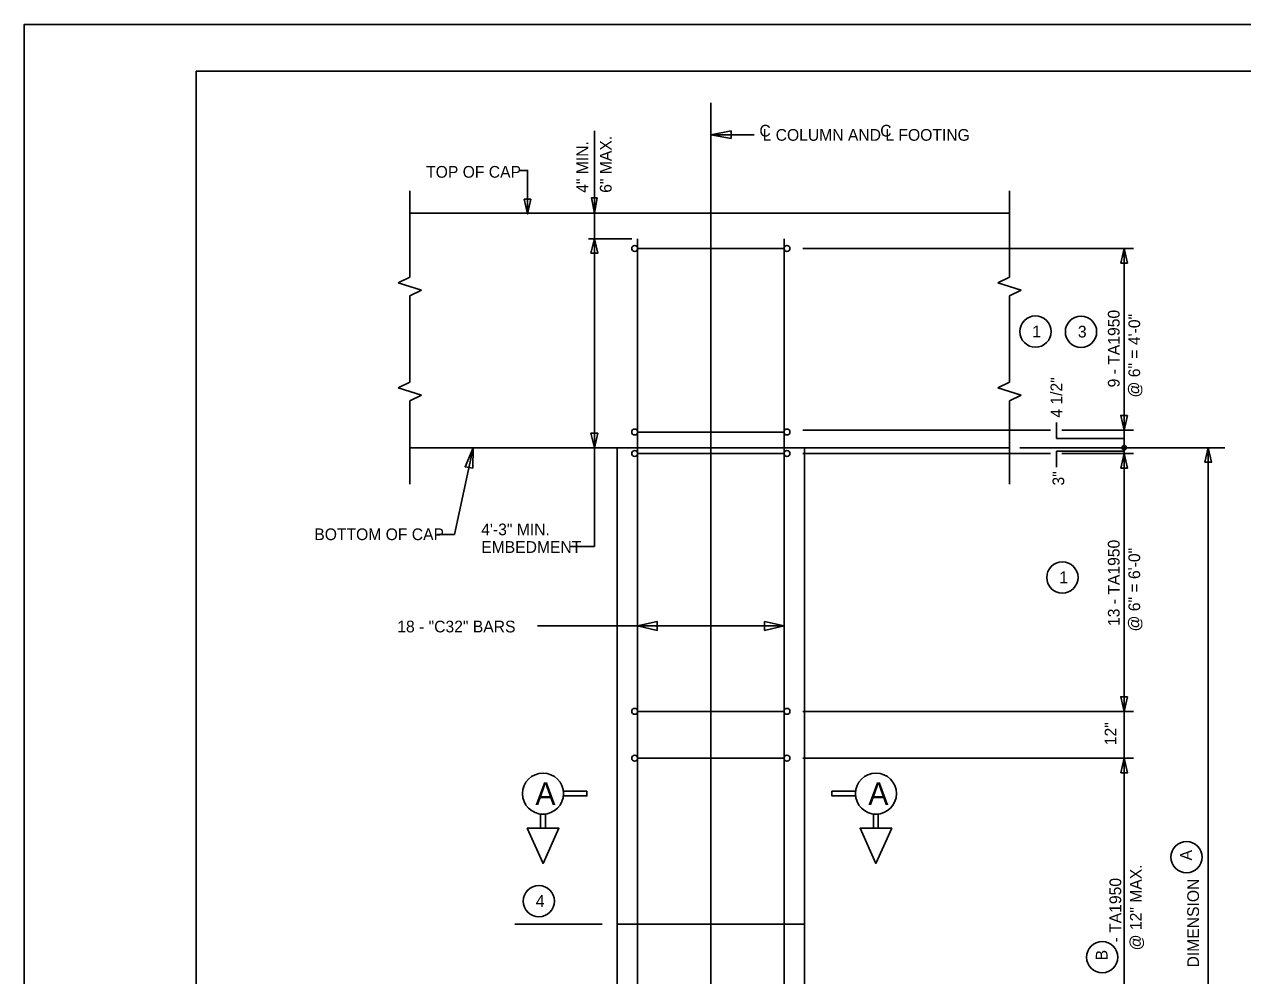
# Model space of a CAD drawing. Extents: x 1970675.2 to 1970711.3, y 796145.2 to 796167.2.
# Drawn here: x 1970675.24 to 1970688.23, y 796157.1 to 796167.25 of the extents above; entities that cross this region are included whole.
import ezdxf

# ---------------------------------------------------------------- set-up
doc = ezdxf.new("R2010")
doc.units = 0
for name, color, linetype in [('BR_AUTO DIMENSION', 7, 'Continuous'), ('BR_BORDER LINES', 7, 'Continuous'), ('BR_CENTER LINES', 7, 'Continuous'), ('BR_CONCRETE', 7, 'Continuous'), ('BR_REBAR', 7, 'Continuous'), ('BR_TEXT', 7, 'Continuous'), ('Default', 7, 'Continuous'), ('Level 31', 7, 'Continuous')]:
    doc.layers.add(name, color=color, linetype=linetype)

msp = doc.modelspace()

# ---------------------------------------------------------------- linework, layer by layer
at = {"layer": 'BR_AUTO DIMENSION'}
for p, q in [((1970681.318, 796166.112), (1970681.318, 796164.961)), ((1970682.561, 796166.069), (1970683.022, 796166.069)), ((1970681.717, 796164.961), (1970681.254, 796164.961)), ((1970681.318, 796164.961), (1970681.318, 796161.677)), ((1970683.541, 796164.857), (1970687.071, 796164.857)), ((1970686.97, 796164.857), (1970686.97, 796153.247)), ((1970686.247, 796162.829), (1970686.247, 796163.002)), ((1970686.97, 796162.92), (1970686.97, 796163.012)), ((1970683.541, 796162.92), (1970686.186, 796162.92)), ((1970686.305, 796162.92), (1970687.071, 796162.92)), ((1970679.827, 796161.807), (1970680.025, 796162.732)), ((1970685.859, 796162.732), (1970688.046, 796162.732)), ((1970686.247, 796162.829), (1970686.97, 796162.829)), ((1970687.866, 796162.732), (1970687.866, 796153.247)), ((1970683.541, 796162.67), (1970686.186, 796162.67)), ((1970686.247, 796162.696), (1970686.97, 796162.696)), ((1970686.247, 796162.696), (1970686.247, 796162.523)), ((1970686.305, 796162.67), (1970687.071, 796162.67)), ((1970686.97, 796162.67), (1970686.97, 796162.543)), ((1970679.64, 796161.807), (1970679.827, 796161.807)), ((1970681.318, 796161.677), (1970681.058, 796161.677)), ((1970680.712, 796160.832), (1970683.342, 796160.832)), ((1970683.541, 796159.92), (1970687.071, 796159.92)), ((1970683.541, 796159.42), (1970687.071, 796159.42)), ((1970680.47, 796157.65), (1970681.4, 796157.65))]:
    msp.add_line(p, q, dxfattribs=at)
for points in [[(1970682.777, 796166.028), (1970682.561, 796166.069), (1970682.777, 796166.111)], [(1970680.641, 796165.381), (1970680.605, 796165.225), (1970680.569, 796165.381)], [(1970681.349, 796165.395), (1970681.318, 796165.232), (1970681.286, 796165.395)], [(1970681.282, 796164.805), (1970681.318, 796164.961), (1970681.354, 796164.805)], [(1970686.934, 796164.701), (1970686.97, 796164.857), (1970687.006, 796164.701)], [(1970687.006, 796163.076), (1970686.97, 796162.92), (1970686.934, 796163.076)], [(1970681.354, 796162.888), (1970681.318, 796162.732), (1970681.282, 796162.888)], [(1970680.02, 796162.512), (1970680.025, 796162.732), (1970679.939, 796162.529)], [(1970687.83, 796162.576), (1970687.866, 796162.732), (1970687.902, 796162.576)], [(1970686.934, 796162.514), (1970686.97, 796162.67), (1970687.006, 796162.514)], [(1970681.987, 796160.784), (1970681.779, 796160.832), (1970681.987, 796160.88)], [(1970683.134, 796160.88), (1970683.342, 796160.832), (1970683.134, 796160.784)], [(1970687.006, 796160.076), (1970686.97, 796159.92), (1970686.934, 796160.076)], [(1970686.934, 796159.264), (1970686.97, 796159.42), (1970687.006, 796159.264)]]:
    msp.add_lwpolyline(points, close=True, dxfattribs=at)
msp.add_lwpolyline([(1970680.605, 796165.225), (1970680.605, 796165.689), (1970680.527, 796165.689)], dxfattribs=at)
for centre, radius in [((1970686.024, 796163.97), 0.167), ((1970686.51, 796163.968), 0.167), ((1970686.97, 796162.732), 0.0235), ((1970686.311, 796161.348), 0.167), ((1970687.636, 796158.365), 0.167), ((1970680.726, 796157.896), 0.167), ((1970686.736, 796157.298), 0.167)]:
    msp.add_circle(centre, radius, dxfattribs=at)
at = {"layer": 'BR_BORDER LINES'}
for p in [(1970710.736, 796166.746), (1970677.07, 796145.746)]:
    msp.add_line(p, (1970677.07, 796166.746), dxfattribs=at)
at = {"layer": 'BR_CENTER LINES'}
msp.add_line((1970682.561, 796151.747), (1970682.561, 796166.409), dxfattribs=at)
at = {"layer": 'BR_CONCRETE'}
for p, q in [((1970679.348, 796165.232), (1970685.748, 796165.232)), ((1970679.348, 796162.732), (1970685.748, 796162.732)), ((1970681.561, 796162.732), (1970681.561, 796153.247)), ((1970683.561, 796162.732), (1970683.561, 796153.247)), ((1970681.561, 796157.65), (1970683.561, 796157.65))]:
    msp.add_line(p, q, dxfattribs=at)
at = {"layer": 'BR_REBAR'}
for p, q in [((1970681.779, 796164.961), (1970681.779, 796154.623)), ((1970683.342, 796164.959), (1970683.342, 796151.679)), ((1970681.779, 796164.857), (1970683.342, 796164.857)), ((1970681.779, 796162.899), (1970683.342, 796162.899)), ((1970681.779, 796162.67), (1970683.342, 796162.67)), ((1970681.779, 796159.92), (1970683.342, 796159.92)), ((1970681.779, 796159.42), (1970683.342, 796159.42))]:
    msp.add_line(p, q, dxfattribs=at)
for centre in [(1970681.748, 796164.857), (1970683.373, 796164.857), (1970681.748, 796162.899), (1970683.373, 796162.899), (1970681.748, 796162.67), (1970683.373, 796162.67), (1970681.748, 796159.92), (1970683.373, 796159.92), (1970681.748, 796159.42), (1970683.373, 796159.42)]:
    msp.add_circle(centre, 0.0313, dxfattribs=at)
at = {"layer": 'BR_TEXT'}
for points in [[(1970681.239, 796159.068), (1970681.239, 796159.018), (1970680.989, 796159.018), (1970680.989, 796159.068)], [(1970683.853, 796159.068), (1970683.853, 796159.018), (1970684.103, 796159.018), (1970684.103, 796159.068)], [(1970680.795, 796158.824), (1970680.795, 796158.674), (1970680.745, 796158.674), (1970680.745, 796158.824)], [(1970684.297, 796158.824), (1970684.297, 796158.674), (1970684.347, 796158.674), (1970684.347, 796158.824)], [(1970680.601, 796158.674), (1970680.77, 796158.299), (1970680.939, 796158.674)], [(1970684.491, 796158.674), (1970684.322, 796158.299), (1970684.153, 796158.674)]]:
    msp.add_lwpolyline(points, close=True, dxfattribs=at)
for centre in [(1970680.77, 796159.043), (1970684.322, 796159.043)]:
    msp.add_circle(centre, 0.219, dxfattribs=at)
at = {"layer": 'Default'}
for p, q in [((1970679.348, 796165.47), (1970679.348, 796164.551)), ((1970685.748, 796165.47), (1970685.748, 796164.551)), ((1970679.223, 796164.49), (1970679.348, 796164.551)), ((1970685.623, 796164.49), (1970685.748, 796164.551)), ((1970679.473, 796164.411), (1970679.223, 796164.49)), ((1970685.873, 796164.411), (1970685.623, 796164.49)), ((1970679.348, 796164.35), (1970679.473, 796164.411)), ((1970679.348, 796163.431), (1970679.348, 796164.35)), ((1970685.748, 796164.35), (1970685.873, 796164.411)), ((1970685.748, 796163.431), (1970685.748, 796164.35)), ((1970679.223, 796163.37), (1970679.348, 796163.431)), ((1970685.623, 796163.37), (1970685.748, 796163.431)), ((1970679.473, 796163.292), (1970679.223, 796163.37)), ((1970679.348, 796163.23), (1970679.473, 796163.292)), ((1970685.873, 796163.292), (1970685.623, 796163.37)), ((1970685.748, 796163.23), (1970685.873, 796163.292)), ((1970679.348, 796162.344), (1970679.348, 796163.23)), ((1970679.348, 796163.17), (1970679.348, 796163.23)), ((1970685.748, 796162.344), (1970685.748, 796163.23)), ((1970685.748, 796163.17), (1970685.748, 796163.23))]:
    msp.add_line(p, q, dxfattribs=at)
at = {"layer": 'Level 31'}
msp.add_lwpolyline([(1970675.236, 796145.246), (1970711.236, 796145.246), (1970711.236, 796167.246), (1970675.236, 796167.246)], close=True, dxfattribs=at)

# ---------------------------------------------------------------- texts
at = {"layer": 'BR_AUTO DIMENSION'}
for s, p in [('4" MIN.', (1970681.252, 796165.45)), ('6" MAX.', (1970681.502, 796165.45))]:
    msp.add_text(s, height=0.125, rotation=90, dxfattribs=at).set_placement(p)
at = {"layer": 'BR_TEXT'}
for s, height, p in [('C', 0.125, (1970683.079, 796166.05)), ('L COLUMN AND L FOOTING', 0.125, (1970683.113, 796166.005)), ('C', 0.125, (1970684.368, 796166.05)), ('TOP OF CAP', 0.125, (1970679.523, 796165.611)), ('1', 0.125, (1970685.99, 796163.909)), ('3', 0.125, (1970686.477, 796163.907)), ('BOTTOM OF CAP', 0.125, (1970678.33, 796161.746)), ('4\'-3" MIN.', 0.125, (1970680.111, 796161.798)), ('EMBEDMENT', 0.125, (1970680.111, 796161.61)), ('1', 0.125, (1970686.278, 796161.287)), ('18 - "C32" BARS', 0.125, (1970679.215, 796160.762)), ('A', 0.24, (1970680.689, 796158.923)), ('A', 0.24, (1970684.241, 796158.923)), ('4', 0.125, (1970680.693, 796157.835))]:
    msp.add_text(s, height=height, dxfattribs=at).set_placement(p)
for s, p in [('9 - TA1950', (1970686.922, 796163.375)), ('@ 6" = 4\'-0"', (1970687.141, 796163.267)), ('4 1/2"', (1970686.31, 796163.052)), ('3"', (1970686.331, 796162.328)), ('13 - TA1950', (1970686.922, 796160.83)), ('@ 6" = 6\'-0"', (1970687.141, 796160.772)), ('12"', (1970686.888, 796159.559)), ('A', (1970687.693, 796158.33)), ('@ 12" MAX.', (1970687.158, 796157.371)), ('  - TA1950', (1970686.939, 796157.363)), ('DIMENSION', (1970687.769, 796157.189)), ('B', (1970686.793, 796157.265))]:
    msp.add_text(s, height=0.125, rotation=90, dxfattribs=at).set_placement(p)

doc.saveas('drawing.dxf')
